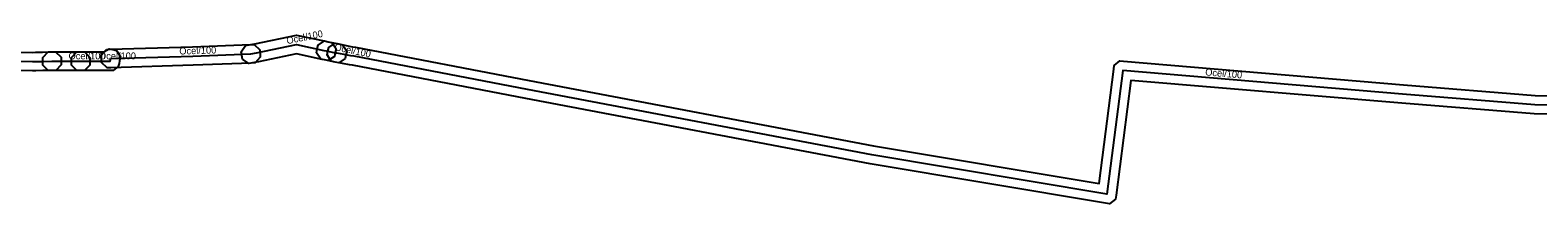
# Model space of a CAD drawing. Extents: x -569373 to -565022, y -1135090 to -1131496.
# Drawn here: x -566086.3 to -565922.5, y -1133791.7 to -1133772.8 of the extents above; entities that cross this region are included whole.
import ezdxf

# ---------------------------------------------------------------- set-up
doc = ezdxf.new("R2010")
doc.units = 0
for name, color, linetype in [('1', 7, 'Continuous'), ('24', 7, 'Continuous'), ('30', 7, 'Continuous')]:
    doc.layers.add(name, color=color, linetype=linetype)

msp = doc.modelspace()

# ---------------------------------------------------------------- linework, layer by layer
at = {"layer": '1'}
for points in [[(-566102.341, -1133773.967), (-566101.93, -1133774.017), (-566092.207, -1133775.19), (-566086.071, -1133775.23), (-566085.731, -1133775.22), (-566084.987, -1133775.21), (-566083.97, -1133775.19), (-566083.556, -1133775.182), (-566082.958, -1133775.756), (-566082.95, -1133776.17), (-566082.942, -1133776.584), (-566083.516, -1133777.182), (-566083.93, -1133777.19), (-566084.953, -1133777.21), (-566085.689, -1133777.22), (-566086.049, -1133777.23), (-566092.333, -1133777.19), (-566102.17, -1133776.003), (-566102.581, -1133775.953), (-566103.093, -1133775.301), (-566103.043, -1133774.89), (-566102.993, -1133774.479)], [(-566078.004, -1133774.913), (-566077.59, -1133774.9), (-566068.674, -1133774.631), (-566062.368, -1133774.391), (-566061.954, -1133774.375), (-566061.347, -1133774.938), (-566061.331, -1133775.352), (-566061.315, -1133775.766), (-566061.878, -1133776.373), (-566062.292, -1133776.389), (-566068.606, -1133776.629), (-566077.53, -1133776.9), (-566077.944, -1133776.912), (-566078.547, -1133776.344), (-566078.56, -1133775.93), (-566078.572, -1133775.516)], [(-566062.924, -1133774.485), (-566062.517, -1133774.408), (-566061.894, -1133774.289), (-566057.357, -1133773.359), (-566054.179, -1133774.03), (-566053.934, -1133774.079), (-566053.528, -1133774.161), (-566053.068, -1133774.85), (-566053.149, -1133775.256), (-566053.231, -1133775.662), (-566053.92, -1133776.122), (-566054.326, -1133776.041), (-566054.581, -1133775.99), (-566057.363, -1133775.401), (-566061.506, -1133776.251), (-566062.143, -1133776.372), (-566062.55, -1133776.449), (-566063.235, -1133775.984), (-566063.312, -1133775.577), (-566063.389, -1133775.17)], [(-566054.333, -1133773.997), (-566053.927, -1133774.081), (-566052.767, -1133774.321), (-566052.361, -1133774.405), (-566051.907, -1133775.097), (-566051.991, -1133775.503), (-566052.075, -1133775.909), (-566052.767, -1133776.363), (-566053.173, -1133776.279), (-566054.333, -1133776.039), (-566054.739, -1133775.955), (-566055.193, -1133775.263), (-566055.109, -1133774.857), (-566055.025, -1133774.451)], [(-566084.364, -1133775.19), (-566083.95, -1133775.19), (-566080.83, -1133775.19), (-566080.416, -1133775.19), (-566079.83, -1133775.776), (-566079.83, -1133776.19), (-566079.83, -1133776.604), (-566080.416, -1133777.19), (-566080.83, -1133777.19), (-566083.95, -1133777.19), (-566084.364, -1133777.19), (-566084.95, -1133776.604), (-566084.95, -1133776.19), (-566084.95, -1133775.776)], [(-566080.6, -1133775.19), (-566078.317, -1133775.19), (-566077.728, -1133774.831), (-566077.325, -1133774.928), (-566076.922, -1133775.025), (-566076.491, -1133775.732), (-566076.588, -1133776.135), (-566076.658, -1133776.425), (-566076.739, -1133776.762), (-566077.284, -1133777.19), (-566077.63, -1133777.19), (-566080.6, -1133777.19), (-566080.83, -1133777.19), (-566081.244, -1133777.19), (-566081.83, -1133776.604), (-566081.83, -1133776.19), (-566081.83, -1133775.776), (-566081.244, -1133775.19), (-566080.83, -1133775.19)]]:
    msp.add_lwpolyline(points, close=True, dxfattribs=at)
msp.add_lwpolyline([(-565909.57, -1133782.02), (-565922.834, -1133781.91), (-565937.232, -1133780.747), (-565966.69, -1133778.267), (-565968.288, -1133790.727), (-565968.342, -1133791.149), (-565968.683, -1133791.403), (-565969.025, -1133791.656), (-565969.444, -1133791.586), (-565995.005, -1133787.335), (-566032.447, -1133780.232), (-566051.277, -1133776.636), (-566051.612, -1133776.587), (-566052.363, -1133776.451), (-566053.178, -1133776.278), (-566053.583, -1133776.192), (-566054.034, -1133775.497), (-566053.948, -1133775.092), (-566053.862, -1133774.687), (-566053.167, -1133774.236), (-566052.762, -1133774.322), (-566051.977, -1133774.489), (-566051.288, -1133774.613), (-566050.943, -1133774.664), (-566032.073, -1133778.268), (-565994.655, -1133785.365), (-565970.14, -1133789.443), (-565968.552, -1133777.063), (-565968.501, -1133776.665), (-565967.876, -1133776.16), (-565967.476, -1133776.194), (-565937.068, -1133778.753), (-565922.746, -1133779.91), (-565909.63, -1133780.02)], dxfattribs=at)
at = {"layer": '24'}
for points in [[(-566062.33, -1133775.39), (-566061.7, -1133775.27), (-566057.36, -1133774.38), (-566054.38, -1133775.01), (-566054.13, -1133775.06)], [(-566102.05, -1133775.01), (-566092.27, -1133776.19), (-566086.06, -1133776.23), (-566085.71, -1133776.22), (-566084.97, -1133776.21), (-566083.95, -1133776.19)], [(-566080.83, -1133776.19), (-566080.6, -1133776.19), (-566077.63, -1133776.19), (-566077.56, -1133775.9)], [(-566077.56, -1133775.9), (-566068.64, -1133775.63), (-566062.33, -1133775.39)], [(-566054.13, -1133775.06), (-566052.97, -1133775.3)], [(-565851.65, -1133776.72), (-565865.27, -1133777.68), (-565875.93, -1133778.91), (-565884.2, -1133779.29), (-565909.6, -1133781.02), (-565922.79, -1133780.91), (-565937.15, -1133779.75), (-565967.56, -1133777.19), (-565969.28, -1133790.6), (-565994.83, -1133786.35), (-566032.26, -1133779.25), (-566051.11, -1133775.65), (-566051.45, -1133775.6), (-566052.17, -1133775.47), (-566052.97, -1133775.3)], [(-566083.95, -1133776.19), (-566080.83, -1133776.19)]]:
    msp.add_lwpolyline(points, dxfattribs=at)

# ---------------------------------------------------------------- texts
at = {"layer": '30'}
for rotation, p in [(11.58893, (-566058.378, -1133774.348)), (348.31063, (-566053.301, -1133774.99)), (1.73376, (-566070.094, -1133775.468)), (355.18802, (-565958.624, -1133777.725))]:
    msp.add_text('Ocel/100', height=0.75, rotation=rotation, dxfattribs=at).set_placement(p)
for p in [(-566082.14, -1133775.99), (-566078.831, -1133775.99)]:
    msp.add_text('Ocel/100', height=0.75, dxfattribs=at).set_placement(p)

doc.saveas('drawing.dxf')
